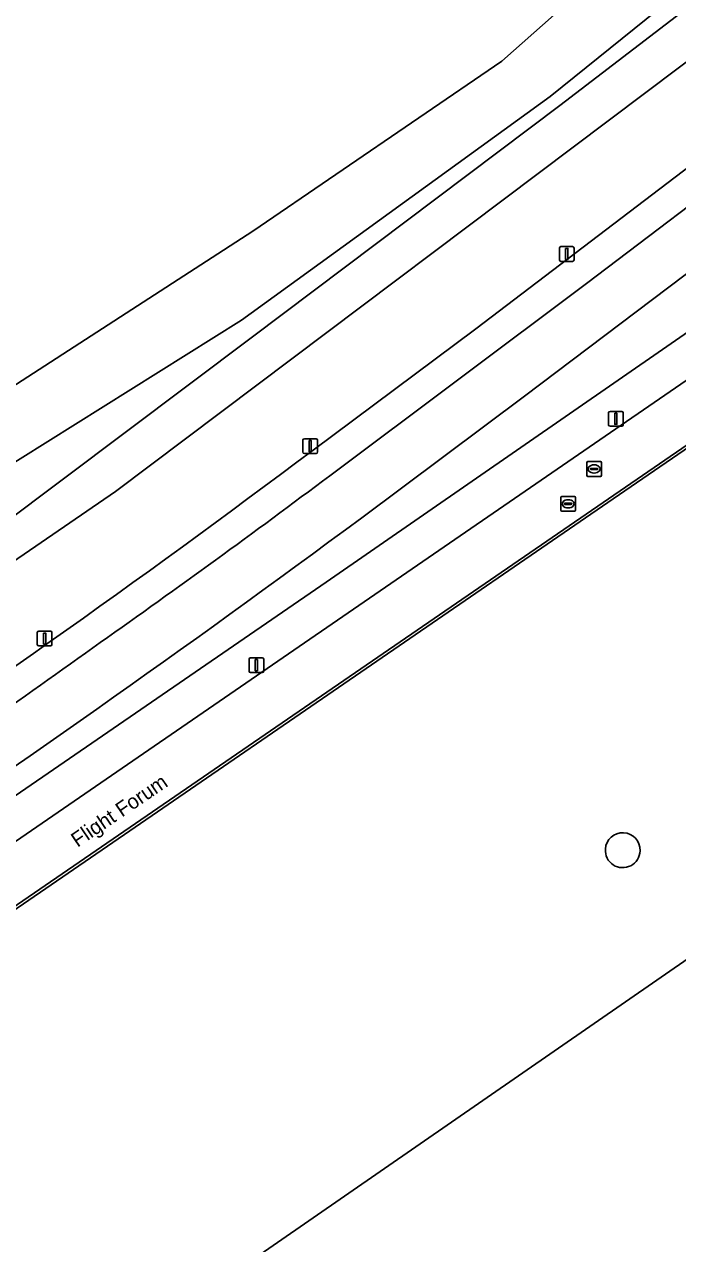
# Model space of a CAD drawing. Extents: x 155018 to 156648, y 383979 to 385733.
# Drawn here: x 155835.7 to 155880, y 384564.6 to 384647.2 of the extents above; entities that cross this region are included whole.
import ezdxf

# ---------------------------------------------------------------- set-up
doc = ezdxf.new("R2010")
doc.units = 0
for name, color, linetype in [('IMGEO_Berm_groen', 7, 'Continuous'), ('IMGEO_Erf', 7, 'Continuous'), ('IMGEO_Fietspad_gesloten', 7, 'Continuous'), ('IMGEO_Groenvoorziening', 7, 'Continuous'), ('IMGEO_Lichtmast', 7, 'Continuous'), ('IMGEO_Lijnafwatering', 7, 'Continuous'), ('IMGEO_Loofbos', 7, 'Continuous'), ('IMGEO_Oever', 7, 'Continuous'), ('IMGEO_Openbare_ruimte_label', 7, 'Continuous'), ('IMGEO_Opslagtank', 7, 'Continuous'), ('IMGEO_Pand', 7, 'Continuous'), ('IMGEO_Rijbaan_lokaal_gesloten', 7, 'Continuous'), ('IMGEO_Rioolput', 7, 'Continuous'), ('IMGEO_Voetpad_gesloten', 7, 'Continuous'), ('IMGEO_Waterloop', 7, 'Continuous')]:
    doc.layers.add(name, color=color, linetype=linetype)

msp = doc.modelspace()

# ---------------------------------------------------------------- linework, layer by layer
at = {"layer": 'IMGEO_Berm_groen'}
for points in [[(155856.161, 384609.448), (155902.301, 384641.367), (155899.948, 384644.959), (155869.596, 384622.038), (155858.583, 384613.801)], [(155903.797, 384639.084), (155902.301, 384641.367), (155856.161, 384609.448), (155766.354, 384547.73), (155757.969, 384542.25)], [(155764.935, 384543.617), (155903.797, 384639.084)], [(155757.969, 384542.25), (155766.354, 384547.73), (155856.161, 384609.448)]]:
    msp.add_lwpolyline(points, dxfattribs=at)
msp.add_arc((155290.304, 385381.493), 955.139, 303.856162, 306.510442, dxfattribs=at)
at = {"layer": 'IMGEO_Erf'}
for points in [[(155933.66, 384655.185), (155766.943, 384540.708)], [(155780.361, 384514.559), (155784.56, 384517.463), (155944.734, 384628.249), (155949.704, 384630.566), (155955.291, 384631.292), (155960.697, 384630.244), (155965.641, 384627.693), (155969.744, 384623.74), (155972.217, 384618.987), (155973.215, 384613.511)]]:
    msp.add_lwpolyline(points, dxfattribs=at)
for centre, start, end in [((155876.254, 384591.293), 357.57858, 177.0013), ((155876.253, 384591.27), 175.91941, 358.66048)]:
    msp.add_arc(centre, 1.174, start, end, dxfattribs=at)
at = {"layer": 'IMGEO_Fietspad_gesloten'}
for points in [[(155934.563, 384673.148), (155917.277, 384661.593), (155901.112, 384650.301), (155885.652, 384638.663), (155873.794, 384629.68), (155856.412, 384616.646)], [(155858.583, 384613.801), (155869.596, 384622.038), (155899.948, 384644.959)]]:
    msp.add_lwpolyline(points, dxfattribs=at)
for centre, radius, start, end in [((155469.79, 385132.029), 644.28, 305.167411, 306.875934), ((155290.304, 385381.493), 955.139, 303.856162, 306.510442), ((155503.01, 385073.966), 577.715, 303.815227, 305.790838)]:
    msp.add_arc(centre, radius, start, end, dxfattribs=at)
at = {"layer": 'IMGEO_Groenvoorziening'}
for points in [[(155855.291, 384618.389), (155866.31, 384626.604), (155893.296, 384647.14), (155912.071, 384660.479)], [(155882.472, 384646.103), (155841.903, 384615.581), (155784.941, 384576.485)]]:
    msp.add_lwpolyline(points, dxfattribs=at)
msp.add_arc((155406.448, 385215.443), 746.949, 303.553818, 306.93448, dxfattribs=at)
at = {"layer": 'IMGEO_Lichtmast'}
for p, q in [((155871.967, 384631.269), (155871.967, 384632.069)), ((155871.967, 384632.069), (155871.967, 384631.269)), ((155872.067, 384632.169), (155872.857, 384632.169)), ((155872.857, 384632.169), (155872.067, 384632.169)), ((155872.957, 384632.069), (155872.957, 384631.269)), ((155872.957, 384631.269), (155872.957, 384632.069)), ((155872.857, 384631.169), (155872.067, 384631.169)), ((155872.067, 384631.169), (155872.857, 384631.169)), ((155875.293, 384620.106), (155875.293, 384620.906)), ((155875.293, 384620.906), (155875.293, 384620.106)), ((155875.393, 384621.006), (155876.183, 384621.006)), ((155876.183, 384621.006), (155875.393, 384621.006)), ((155876.283, 384620.906), (155876.283, 384620.106)), ((155876.283, 384620.106), (155876.283, 384620.906)), ((155876.183, 384620.006), (155875.393, 384620.006)), ((155875.393, 384620.006), (155876.183, 384620.006)), ((155854.594, 384618.259), (155854.594, 384619.059)), ((155854.594, 384619.059), (155854.594, 384618.259)), ((155854.694, 384619.159), (155855.484, 384619.159)), ((155855.484, 384619.159), (155854.694, 384619.159)), ((155855.584, 384619.059), (155855.584, 384618.259)), ((155855.584, 384618.259), (155855.584, 384619.059)), ((155855.484, 384618.159), (155854.694, 384618.159)), ((155854.694, 384618.159), (155855.484, 384618.159)), ((155836.61, 384605.218), (155836.61, 384606.018)), ((155836.61, 384606.018), (155836.61, 384605.218)), ((155836.71, 384606.118), (155837.5, 384606.118)), ((155837.5, 384606.118), (155836.71, 384606.118)), ((155837.6, 384606.018), (155837.6, 384605.218)), ((155837.6, 384605.218), (155837.6, 384606.018)), ((155837.5, 384605.118), (155836.71, 384605.118)), ((155836.71, 384605.118), (155837.5, 384605.118)), ((155850.949, 384603.415), (155850.949, 384604.215)), ((155850.949, 384604.215), (155850.949, 384603.415)), ((155851.049, 384604.315), (155851.839, 384604.315)), ((155851.839, 384604.315), (155851.049, 384604.315)), ((155851.939, 384604.215), (155851.939, 384603.415)), ((155851.939, 384603.415), (155851.939, 384604.215)), ((155851.839, 384603.315), (155851.049, 384603.315)), ((155851.049, 384603.315), (155851.839, 384603.315))]:
    msp.add_line(p, q, dxfattribs=at)
for points in [[(155872.387, 384632.044), (155872.537, 384632.044), (155872.537, 384631.294), (155872.387, 384631.294), (155872.387, 384632.044)], [(155875.713, 384620.881), (155875.863, 384620.881), (155875.863, 384620.131), (155875.713, 384620.131), (155875.713, 384620.881)], [(155855.014, 384619.034), (155855.164, 384619.034), (155855.164, 384618.284), (155855.014, 384618.284), (155855.014, 384619.034)], [(155837.03, 384605.993), (155837.18, 384605.993), (155837.18, 384605.243), (155837.03, 384605.243), (155837.03, 384605.993)], [(155851.369, 384604.19), (155851.519, 384604.19), (155851.519, 384603.44), (155851.369, 384603.44), (155851.369, 384604.19)]]:
    msp.add_lwpolyline(points, dxfattribs=at)
for centre, start, end in [((155872.067, 384632.069), 90, 180), ((155872.067, 384632.069), 90, 180), ((155872.857, 384632.069), 0, 90), ((155872.857, 384632.069), 360, 90), ((155872.067, 384631.269), 180, 270), ((155872.067, 384631.269), 180, 270), ((155872.857, 384631.269), 270, 0), ((155872.857, 384631.269), 270, 0), ((155875.393, 384620.906), 90, 180), ((155875.393, 384620.906), 90, 180), ((155876.183, 384620.906), 0, 90), ((155876.183, 384620.906), 360, 90), ((155875.393, 384620.106), 180, 270), ((155875.393, 384620.106), 180, 270), ((155876.183, 384620.106), 270, 0), ((155876.183, 384620.106), 270, 0), ((155854.694, 384619.059), 90, 180), ((155854.694, 384619.059), 90, 180), ((155855.484, 384619.059), 0, 90), ((155855.484, 384619.059), 360, 90), ((155854.694, 384618.259), 180, 270), ((155854.694, 384618.259), 180, 270), ((155855.484, 384618.259), 270, 0), ((155855.484, 384618.259), 270, 0), ((155836.71, 384606.018), 90, 180), ((155836.71, 384606.018), 90, 180), ((155837.5, 384606.018), 0, 90), ((155837.5, 384606.018), 360, 90), ((155836.71, 384605.218), 180, 270), ((155836.71, 384605.218), 180, 270), ((155837.5, 384605.218), 270, 0), ((155837.5, 384605.218), 270, 0), ((155851.049, 384604.215), 90, 180), ((155851.049, 384604.215), 90, 180), ((155851.839, 384604.215), 0, 90), ((155851.839, 384604.215), 360, 90), ((155851.049, 384603.415), 180, 270), ((155851.049, 384603.415), 180, 270), ((155851.839, 384603.415), 270, 0), ((155851.839, 384603.415), 270, 0)]:
    msp.add_arc(centre, 0.1, start, end, dxfattribs=at)
at = {"layer": 'IMGEO_Lijnafwatering'}
for points in [[(155891.963, 384626.311), (155875.599, 384615.074)], [(155875.599, 384615.074), (155859.235, 384603.838)], [(155859.235, 384603.838), (155842.871, 384592.601)], [(155842.871, 384592.601), (155826.507, 384581.365)]]:
    msp.add_lwpolyline(points, dxfattribs=at)
at = {"layer": 'IMGEO_Loofbos'}
msp.add_lwpolyline([(155735.166, 384564.977), (155736.696, 384565.842), (155755.416, 384578.562), (155789.927, 384598.773), (155809.853, 384608.664), (155828.907, 384618.792), (155851.212, 384633.218), (155868.067, 384644.731), (155880.669, 384655.905), (155884.287, 384661.002), (155885.599, 384664.421), (155886.023, 384668.117), (155878.301, 384689.953), (155869.411, 384709.653)], dxfattribs=at)
at = {"layer": 'IMGEO_Oever'}
for points in [[(155784.941, 384576.485), (155841.903, 384615.581), (155882.472, 384646.103), (155889.727, 384651.285), (155905.558, 384662.593), (155908.955, 384663.068), (155911.593, 384664.218), (155911.925, 384666.124), (155911.398, 384666.967), (155910.694, 384668.093), (155910.636, 384668.144), (155908.457, 384670.037), (155905.323, 384672.209), (155890.56, 384700.593), (155884.794, 384711.78), (155879.509, 384721.798), (155877.775, 384721.093)], [(155869.411, 384709.653), (155878.301, 384689.953), (155886.023, 384668.117), (155885.599, 384664.421), (155884.287, 384661.002), (155880.669, 384655.905), (155868.067, 384644.731), (155851.212, 384633.218), (155828.907, 384618.792), (155809.853, 384608.664), (155789.927, 384598.773), (155755.416, 384578.562), (155736.696, 384565.842), (155735.166, 384564.977), (155731.69, 384563.012), (155727.128, 384559.109), (155725.044, 384554.696), (155726.272, 384552.123), (155732.864, 384546.32), (155733.143, 384546.074), (155737.689, 384539.966), (155745.558, 384546.234)], [(155885.585, 384652.161), (155872, 384641.72), (155851.192, 384626.049), (155833.993, 384613.165), (155809.177, 384596.365), (155787.522, 384581.742), (155765.89, 384566.283), (155752.602, 384556.128), (155747.674, 384551.657), (155738.328, 384543.645), (155734.422, 384547.424), (155734.04, 384547.829), (155731.622, 384549.808), (155729.546, 384553.33), (155736.137, 384558.152), (155743.052, 384561.974), (155761.147, 384574.65), (155782.886, 384587.606), (155806.374, 384601.46), (155831.684, 384615.442), (155850.435, 384627.197), (155871.338, 384642.331), (155884.346, 384652.842)]]:
    msp.add_lwpolyline(points, dxfattribs=at)
at = {"layer": 'IMGEO_Opslagtank'}
for centre, start, end in [((155876.254, 384591.293), 357.57858, 177.0013), ((155876.253, 384591.27), 175.91941, 358.66048)]:
    msp.add_arc(centre, 1.174, start, end, dxfattribs=at)
at = {"layer": 'IMGEO_Pand'}
msp.add_lwpolyline([(155973.215, 384613.511), (155972.217, 384618.987), (155969.744, 384623.74), (155965.641, 384627.693), (155960.697, 384630.244), (155955.291, 384631.292), (155949.704, 384630.566), (155944.734, 384628.249), (155784.56, 384517.463), (155780.361, 384514.559)], dxfattribs=at)
at = {"layer": 'IMGEO_Rijbaan_lokaal_gesloten'}
for points in [[(155933.66, 384655.185), (155931.628, 384658.064), (155928.339, 384655.895), (155923.022, 384652.232), (155915.826, 384647.303), (155915.465, 384647.058), (155908.41, 384642.273), (155905.492, 384640.255), (155903.797, 384639.084), (155764.935, 384543.617)], [(155766.943, 384540.708), (155933.66, 384655.185)]]:
    msp.add_lwpolyline(points, dxfattribs=at)
at = {"layer": 'IMGEO_Rioolput'}
for p, q in [((155873.815, 384616.68), (155873.815, 384617.532)), ((155873.89, 384617.606), (155874.742, 384617.606)), ((155874.074, 384617.1), (155874.074, 384617.112)), ((155874.512, 384617.063), (155874.114, 384617.063)), ((155874.117, 384617.149), (155874.515, 384617.149)), ((155874.303, 384617.386), (155874.328, 384617.386)), ((155874.558, 384617.112), (155874.558, 384617.1)), ((155874.816, 384617.532), (155874.816, 384616.68)), ((155874.742, 384616.606), (155873.89, 384616.606)), ((155874.326, 384616.826), (155874.301, 384616.826)), ((155872.059, 384614.32), (155872.059, 384615.172)), ((155872.134, 384615.246), (155872.986, 384615.246)), ((155872.318, 384614.74), (155872.318, 384614.752)), ((155872.756, 384614.703), (155872.358, 384614.703)), ((155872.361, 384614.789), (155872.759, 384614.789)), ((155872.547, 384615.026), (155872.572, 384615.026)), ((155872.802, 384614.752), (155872.802, 384614.74)), ((155873.06, 384615.172), (155873.06, 384614.32)), ((155872.986, 384614.246), (155872.134, 384614.246)), ((155872.57, 384614.466), (155872.545, 384614.466))]:
    msp.add_line(p, q, dxfattribs=at)
for points in [[(155873.815, 384616.68), (155873.815, 384617.532)], [(155873.89, 384617.606), (155874.742, 384617.606)], [(155874.816, 384617.532), (155874.816, 384616.68)], [(155874.742, 384616.606), (155873.89, 384616.606)], [(155872.059, 384614.32), (155872.059, 384615.172)], [(155872.134, 384615.246), (155872.986, 384615.246)], [(155873.06, 384615.172), (155873.06, 384614.32)], [(155872.986, 384614.246), (155872.134, 384614.246)]]:
    msp.add_lwpolyline(points, dxfattribs=at)
for centre, radius, start, end in [((155873.892, 384617.53), 0.0765, 91.55205, 178.44795), ((155873.892, 384617.53), 0.0765, 91.55205, 178.44795), ((155874.114, 384617.109), 0.0403, 85.87752, 175.75265), ((155874.111, 384617.099), 0.0366, 178.93798, 274.71019), ((155874.515, 384617.106), 0.043, 264.86636, 352.45326), ((155874.519, 384617.111), 0.0386, 1.73085, 96.63898), ((155874.74, 384617.53), 0.0765, 1.55205, 88.44795), ((155874.74, 384617.53), 0.0765, 1.55205, 88.44795), ((155873.892, 384616.682), 0.0765, 181.55205, 268.44795), ((155873.892, 384616.682), 0.0765, 181.55205, 268.44795), ((155874.74, 384616.682), 0.0765, 271.55205, 358.44795), ((155874.74, 384616.682), 0.0765, 271.55205, 358.44795), ((155872.136, 384615.17), 0.0765, 91.55205, 178.44795), ((155872.136, 384615.17), 0.0765, 91.55205, 178.44795), ((155872.358, 384614.749), 0.0403, 85.87752, 175.75265), ((155872.355, 384614.739), 0.0366, 178.93798, 274.71019), ((155872.759, 384614.746), 0.043, 264.86636, 352.45326), ((155872.763, 384614.751), 0.0386, 1.73085, 96.63898), ((155872.984, 384615.17), 0.0765, 1.55205, 88.44795), ((155872.984, 384615.17), 0.0765, 1.55205, 88.44795), ((155872.136, 384614.322), 0.0765, 181.55205, 268.44795), ((155872.136, 384614.322), 0.0765, 181.55205, 268.44795), ((155872.984, 384614.322), 0.0765, 271.55205, 358.44795), ((155872.984, 384614.322), 0.0765, 271.55205, 358.44795)]:
    msp.add_arc(centre, radius, start, end, dxfattribs=at)
for centre, major_axis, ratio, start_param, end_param in [((155874.302, 384617.106), (-0.387, 0.002), 0.722429, 4.712389, 7.853982), ((155874.327, 384617.106), (-0.39, 0.002), 0.717154, 1.570796, 4.712389), ((155872.546, 384614.746), (-0.387, 0.002), 0.722429, 4.712389, 7.853982), ((155872.571, 384614.746), (-0.39, 0.002), 0.717154, 1.570796, 4.712389)]:
    msp.add_ellipse(centre, major_axis=major_axis, ratio=ratio, start_param=start_param, end_param=end_param, dxfattribs=at)
at = {"layer": 'IMGEO_Voetpad_gesloten'}
for points in [[(155935.867, 384676.626), (155927.38, 384670.844), (155922.992, 384667.963), (155915.314, 384662.635), (155912.071, 384660.479), (155893.296, 384647.14), (155866.31, 384626.604), (155855.291, 384618.389)], [(155856.412, 384616.646), (155873.794, 384629.68), (155885.652, 384638.663), (155901.112, 384650.301), (155917.277, 384661.593), (155934.563, 384673.148)]]:
    msp.add_lwpolyline(points, dxfattribs=at)
for centre, radius, start, end in [((155406.448, 385215.443), 746.949, 303.553818, 306.93448), ((155469.79, 385132.029), 644.28, 305.167411, 306.875934), ((155503.01, 385073.966), 577.715, 303.815227, 305.790838)]:
    msp.add_arc(centre, radius, start, end, dxfattribs=at)
at = {"layer": 'IMGEO_Waterloop'}
msp.add_lwpolyline([(155884.346, 384652.842), (155871.338, 384642.331), (155850.435, 384627.197), (155831.684, 384615.442), (155806.374, 384601.46), (155782.886, 384587.606), (155761.147, 384574.65), (155743.052, 384561.974), (155736.137, 384558.152), (155729.546, 384553.33), (155731.622, 384549.808), (155734.04, 384547.829), (155734.422, 384547.424), (155738.328, 384543.645), (155747.674, 384551.657), (155752.602, 384556.128), (155765.89, 384566.283), (155787.522, 384581.742), (155809.177, 384596.365), (155833.993, 384613.165), (155851.192, 384626.049), (155872, 384641.72), (155885.585, 384652.161)], dxfattribs=at)

# ---------------------------------------------------------------- texts
at = {"layer": 'IMGEO_Openbare_ruimte_label'}
msp.add_text('Flight Forum', height=1, rotation=34.19864, dxfattribs=at).set_placement((155839.329, 384591.443))

doc.saveas('drawing.dxf')
